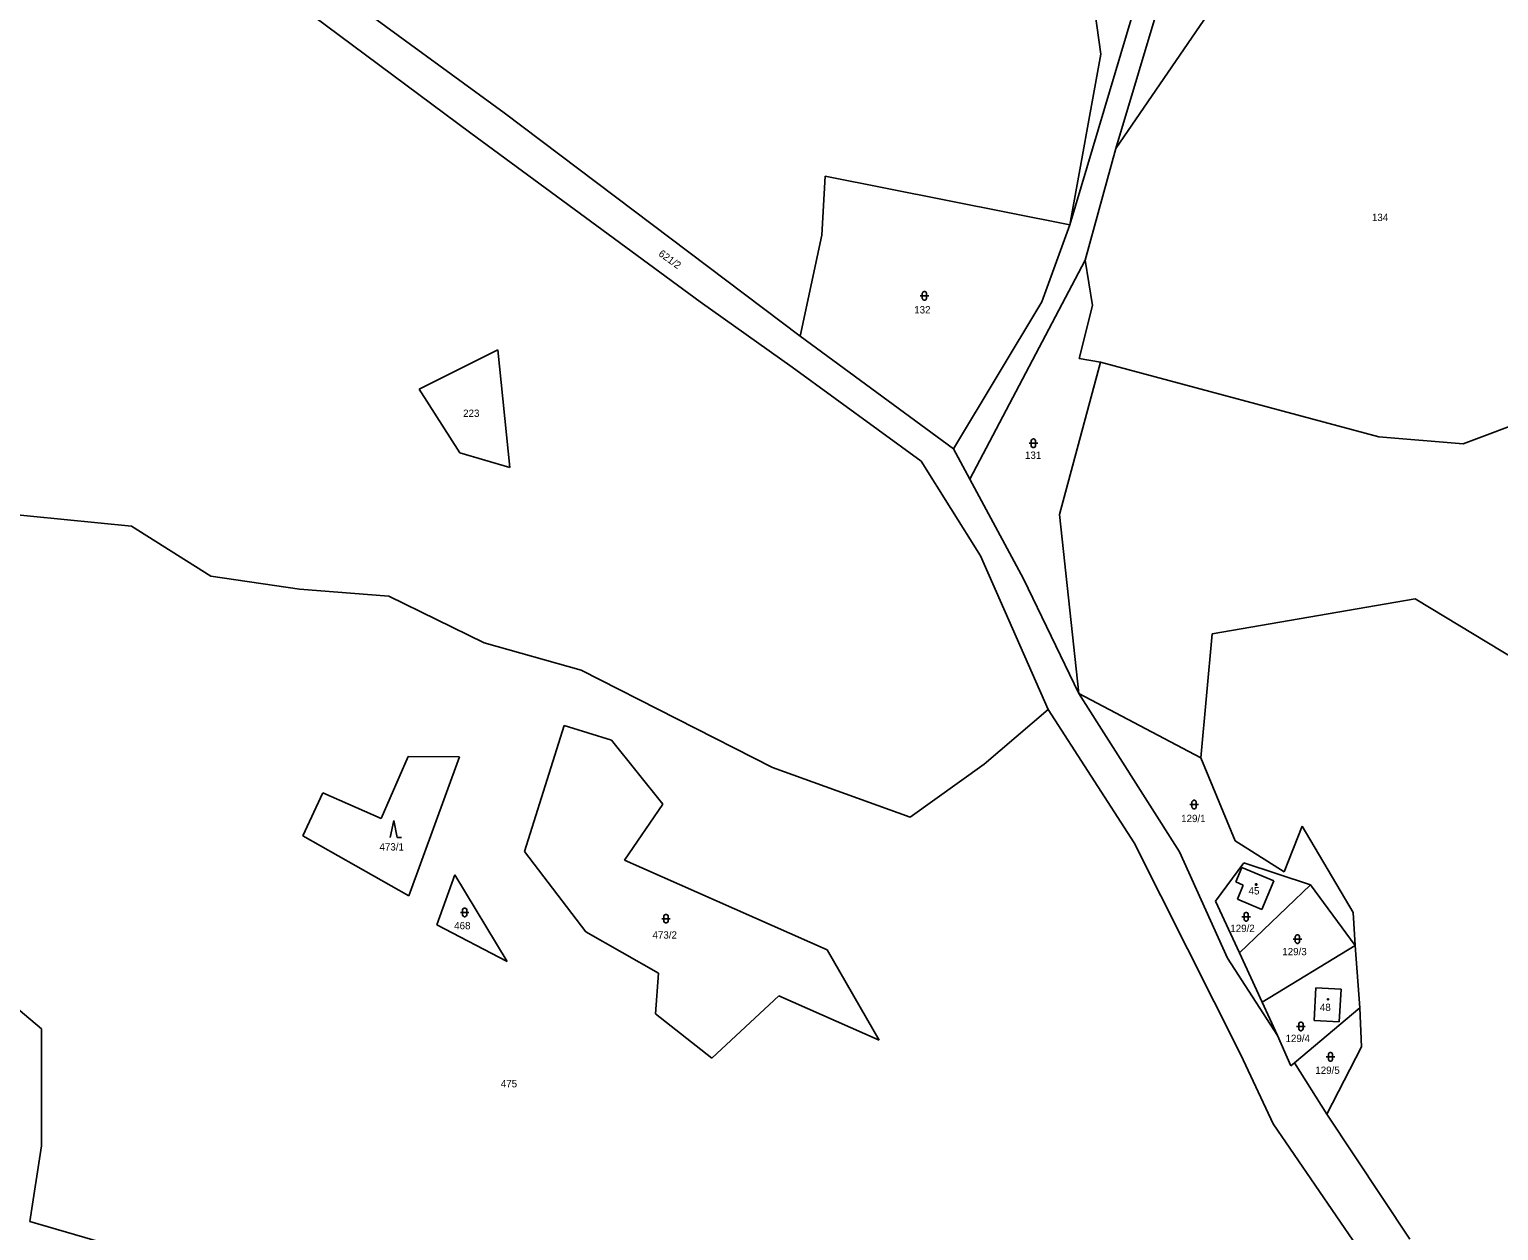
# Model space of a CAD drawing. Extents: x -794421 to -792735, y -1117671 to -1115559.
# Drawn here: x -793818.1 to -793476.5, y -1116696.2 to -1116417 of the extents above; entities that cross this region are included whole.
import ezdxf

# ---------------------------------------------------------------- set-up
doc = ezdxf.new("R2010")
doc.units = 0
for name, color, linetype in [('Vrstva 1', 7, 'Continuous'), ('Vrstva 14', 7, 'Continuous'), ('Vrstva 15', 7, 'Continuous'), ('Vrstva 23', 7, 'Continuous'), ('Vrstva 25', 7, 'Continuous')]:
    doc.layers.add(name, color=color, linetype=linetype)

msp = doc.modelspace()

# ---------------------------------------------------------------- linework, layer by layer
at = {"layer": 'Vrstva 1'}
for p, q in [((-793565.49, -1116444.67), (-793533.59, -1116338.16)), ((-793817.71, -1116356.03), (-793707.67, -1116436.43)), ((-793820.52, -1116362.92), (-793715.41, -1116441.11)), ((-793573.29, -1116390.8), (-793568.98, -1116422.79)), ((-793556.19, -1116395.36), (-793576.18, -1116462.41)), ((-793565.49, -1116444.67), (-793539.73, -1116407.1)), ((-793568.98, -1116422.79), (-793576.18, -1116462.41)), ((-793707.67, -1116436.43), (-793638.86, -1116488.32)), ((-793715.41, -1116441.11), (-793662.08, -1116480.35)), ((-793572.59, -1116470.68), (-793565.49, -1116444.67)), ((-793633.79, -1116464.83), (-793633.04, -1116451.11)), ((-793633.04, -1116451.11), (-793576.18, -1116462.41)), ((-793576.18, -1116462.41), (-793582.65, -1116480.35)), ((-793638.86, -1116488.32), (-793633.79, -1116464.83)), ((-793599.39, -1116521.55), (-793572.59, -1116470.68)), ((-793572.59, -1116470.68), (-793570.88, -1116481.22)), ((-793662.08, -1116480.35), (-793640.75, -1116495.51)), ((-793582.65, -1116480.35), (-793603.22, -1116514.51)), ((-793570.88, -1116481.22), (-793573.97, -1116493.48)), ((-793727.46, -1116500.6), (-793709.18, -1116491.49)), ((-793709.18, -1116491.49), (-793706.36, -1116518.83)), ((-793603.22, -1116514.51), (-793638.86, -1116488.32)), ((-793569.05, -1116494.39), (-793578.55, -1116529.8)), ((-793573.97, -1116493.48), (-793569.05, -1116494.39)), ((-793504.33, -1116511.72), (-793569.05, -1116494.39)), ((-793640.75, -1116495.51), (-793610.73, -1116517.36)), ((-793717.98, -1116515.4), (-793727.46, -1116500.6)), ((-793468.63, -1116507.3), (-793484.73, -1116513.33)), ((-793484.73, -1116513.33), (-793504.33, -1116511.72)), ((-793706.36, -1116518.83), (-793717.98, -1116515.4)), ((-793603.22, -1116514.51), (-793599.39, -1116521.55)), ((-793610.73, -1116517.36), (-793596.97, -1116539.36)), ((-793586.9, -1116544.73), (-793599.39, -1116521.55)), ((-793839.41, -1116527.98), (-793794.32, -1116532.47)), ((-793794.32, -1116532.47), (-793775.91, -1116544.13)), ((-793578.55, -1116529.8), (-793574.06, -1116571.38)), ((-793596.97, -1116539.36), (-793581.18, -1116575.07)), ((-793775.91, -1116544.13), (-793755.23, -1116547.16)), ((-793574.06, -1116571.38), (-793586.9, -1116544.73)), ((-793755.23, -1116547.16), (-793734.46, -1116548.75)), ((-793734.46, -1116548.75), (-793712.33, -1116559.56)), ((-793543.04, -1116557.47), (-793495.85, -1116549.36)), ((-793495.85, -1116549.36), (-793420.04, -1116595.36)), ((-793712.33, -1116559.56), (-793689.8, -1116565.98)), ((-793545.72, -1116586.36), (-793543.04, -1116557.47)), ((-793689.8, -1116565.98), (-793645.3, -1116588.59)), ((-793574.06, -1116571.38), (-793545.72, -1116586.36)), ((-793574.06, -1116571.38), (-793550.69, -1116608.2)), ((-793596.12, -1116587.78), (-793581.18, -1116575.07)), ((-793581.18, -1116575.07), (-793561.2, -1116606.1)), ((-793702.95, -1116608.11), (-793693.75, -1116578.84)), ((-793693.75, -1116578.84), (-793682.71, -1116582.26)), ((-793682.71, -1116582.26), (-793670.77, -1116597.08)), ((-793736.31, -1116600.42), (-793729.99, -1116586.05)), ((-793729.99, -1116586.05), (-793718.09, -1116586.11)), ((-793718.09, -1116586.11), (-793729.87, -1116618.38)), ((-793545.72, -1116586.36), (-793537.76, -1116605.64)), ((-793645.3, -1116588.59), (-793613.3, -1116600.12)), ((-793613.3, -1116600.12), (-793596.12, -1116587.78)), ((-793754.46, -1116604.44), (-793749.83, -1116594.43)), ((-793749.83, -1116594.43), (-793736.31, -1116600.42)), ((-793670.77, -1116597.08), (-793679.71, -1116610.15)), ((-793526.36, -1116612.82), (-793522.13, -1116602.23)), ((-793522.13, -1116602.23), (-793510.33, -1116622.28)), ((-793729.87, -1116618.38), (-793754.46, -1116604.44)), ((-793561.2, -1116606.1), (-793536.44, -1116655.39)), ((-793537.76, -1116605.64), (-793526.36, -1116612.82)), ((-793688.69, -1116626.8), (-793702.95, -1116608.11)), ((-793679.71, -1116610.15), (-793632.55, -1116630.98)), ((-793550.69, -1116608.2), (-793539.5, -1116632.92)), ((-793542.31, -1116619.66), (-793535.68, -1116610.77)), ((-793535.68, -1116610.77), (-793520.23, -1116615.82)), ((-793723.31, -1116625.18), (-793719.14, -1116613.55)), ((-793719.14, -1116613.55), (-793706.96, -1116633.65)), ((-793537.55, -1116615.19), (-793536.18, -1116611.85)), ((-793536.18, -1116611.85), (-793528.75, -1116614.91)), ((-793535.84, -1116615.95), (-793537.55, -1116615.19)), ((-793537.19, -1116619.18), (-793535.84, -1116615.95)), ((-793520.23, -1116615.82), (-793536.73, -1116631.68)), ((-793528.75, -1116614.91), (-793531.53, -1116621.55)), ((-793520.23, -1116615.82), (-793509.84, -1116629.98)), ((-793536.73, -1116631.68), (-793542.31, -1116619.66)), ((-793531.53, -1116621.55), (-793537.19, -1116619.18)), ((-793510.33, -1116622.28), (-793509.84, -1116629.98)), ((-793706.96, -1116633.65), (-793723.31, -1116625.18)), ((-793671.82, -1116636.39), (-793688.69, -1116626.8)), ((-793632.55, -1116630.98), (-793620.47, -1116651.92)), ((-793509.84, -1116629.98), (-793531.46, -1116643.1)), ((-793509.84, -1116629.98), (-793508.72, -1116644.42)), ((-793539.5, -1116632.92), (-793527.92, -1116650.91)), ((-793531.46, -1116643.1), (-793536.73, -1116631.68)), ((-793672.52, -1116645.82), (-793671.82, -1116636.39)), ((-793826.93, -1116639.52), (-793815.21, -1116649.33)), ((-793643.81, -1116641.63), (-793659.41, -1116656.16)), ((-793620.47, -1116651.92), (-793643.81, -1116641.63)), ((-793519.35, -1116647.36), (-793518.94, -1116639.78)), ((-793518.94, -1116639.78), (-793513.12, -1116640.07)), ((-793513.12, -1116640.07), (-793513.51, -1116647.67)), ((-793531.46, -1116643.1), (-793527.92, -1116650.91)), ((-793508.72, -1116644.42), (-793523.95, -1116657.24)), ((-793508.72, -1116644.42), (-793508.34, -1116653.49)), ((-793659.41, -1116656.16), (-793672.52, -1116645.82)), ((-793513.51, -1116647.67), (-793519.35, -1116647.36)), ((-793815.21, -1116649.33), (-793815.21, -1116676.5)), ((-793527.92, -1116650.91), (-793524.75, -1116657.91)), ((-793536.44, -1116655.39), (-793528.9, -1116671.42)), ((-793508.34, -1116653.49), (-793516.41, -1116669.13)), ((-793523.95, -1116657.24), (-793524.75, -1116657.91)), ((-793516.41, -1116669.13), (-793523.95, -1116657.24)), ((-793516.41, -1116669.13), (-793497.1, -1116698.22)), ((-793528.9, -1116671.42), (-793509.4, -1116699.91)), ((-793815.21, -1116676.5), (-793817.93, -1116694.07)), ((-793817.93, -1116694.07), (-793767.94, -1116708.64))]:
    msp.add_line(p, q, dxfattribs=at)
at = {"layer": 'Vrstva 23'}
for p, q in [((-793610.26, -1116478.03), (-793610.06, -1116477.93)), ((-793610.06, -1116477.93), (-793609.86, -1116477.93)), ((-793609.86, -1116477.93), (-793609.66, -1116478.03)), ((-793610.96, -1116478.93), (-793608.96, -1116478.93)), ((-793610.46, -1116478.33), (-793610.36, -1116478.13)), ((-793610.46, -1116479.53), (-793610.46, -1116478.33)), ((-793610.36, -1116479.73), (-793610.46, -1116479.53)), ((-793610.36, -1116478.13), (-793610.26, -1116478.03)), ((-793610.26, -1116479.83), (-793610.36, -1116479.73)), ((-793610.06, -1116479.93), (-793610.26, -1116479.83)), ((-793609.86, -1116479.93), (-793610.06, -1116479.93)), ((-793609.66, -1116479.83), (-793609.86, -1116479.93)), ((-793609.66, -1116478.03), (-793609.56, -1116478.13)), ((-793609.56, -1116479.73), (-793609.66, -1116479.83)), ((-793609.56, -1116478.13), (-793609.46, -1116478.33)), ((-793609.46, -1116479.53), (-793609.56, -1116479.73)), ((-793609.46, -1116478.33), (-793609.46, -1116479.53)), ((-793585.64, -1116513.21), (-793583.64, -1116513.21)), ((-793585.14, -1116512.61), (-793585.04, -1116512.41)), ((-793585.14, -1116513.81), (-793585.14, -1116512.61)), ((-793585.04, -1116514.01), (-793585.14, -1116513.81)), ((-793585.04, -1116512.41), (-793584.94, -1116512.31)), ((-793584.94, -1116514.11), (-793585.04, -1116514.01)), ((-793584.94, -1116512.31), (-793584.74, -1116512.21)), ((-793584.74, -1116514.21), (-793584.94, -1116514.11)), ((-793584.74, -1116512.21), (-793584.54, -1116512.21)), ((-793584.54, -1116514.21), (-793584.74, -1116514.21)), ((-793584.54, -1116512.21), (-793584.34, -1116512.31)), ((-793584.34, -1116514.11), (-793584.54, -1116514.21)), ((-793584.34, -1116512.31), (-793584.24, -1116512.41)), ((-793584.24, -1116514.01), (-793584.34, -1116514.11)), ((-793584.24, -1116512.41), (-793584.14, -1116512.61)), ((-793584.14, -1116513.81), (-793584.24, -1116514.01)), ((-793584.14, -1116512.61), (-793584.14, -1116513.81)), ((-793548.27, -1116597.19), (-793546.27, -1116597.19)), ((-793547.77, -1116596.59), (-793547.67, -1116596.39)), ((-793547.77, -1116597.79), (-793547.77, -1116596.59)), ((-793547.67, -1116596.39), (-793547.57, -1116596.29)), ((-793547.57, -1116596.29), (-793547.37, -1116596.19)), ((-793547.37, -1116596.19), (-793547.17, -1116596.19)), ((-793547.17, -1116596.19), (-793546.97, -1116596.29)), ((-793546.97, -1116596.29), (-793546.87, -1116596.39)), ((-793546.87, -1116596.39), (-793546.77, -1116596.59)), ((-793546.77, -1116596.59), (-793546.77, -1116597.79)), ((-793734.17, -1116604.88), (-793733.37, -1116600.88)), ((-793733.37, -1116600.88), (-793732.57, -1116604.88)), ((-793547.67, -1116597.99), (-793547.77, -1116597.79)), ((-793547.57, -1116598.09), (-793547.67, -1116597.99)), ((-793547.37, -1116598.19), (-793547.57, -1116598.09)), ((-793547.17, -1116598.19), (-793547.37, -1116598.19)), ((-793546.97, -1116598.09), (-793547.17, -1116598.19)), ((-793546.87, -1116597.99), (-793546.97, -1116598.09)), ((-793546.77, -1116597.79), (-793546.87, -1116597.99)), ((-793732.57, -1116604.88), (-793731.57, -1116604.88)), ((-793717.26, -1116621.45), (-793717.16, -1116621.35)), ((-793717.16, -1116621.35), (-793716.96, -1116621.25)), ((-793716.96, -1116621.25), (-793716.76, -1116621.25)), ((-793716.76, -1116621.25), (-793716.56, -1116621.35)), ((-793716.56, -1116621.35), (-793716.46, -1116621.45)), ((-793717.86, -1116622.25), (-793715.86, -1116622.25)), ((-793717.36, -1116621.65), (-793717.26, -1116621.45)), ((-793717.36, -1116622.85), (-793717.36, -1116621.65)), ((-793717.26, -1116623.05), (-793717.36, -1116622.85)), ((-793717.16, -1116623.15), (-793717.26, -1116623.05)), ((-793716.96, -1116623.25), (-793717.16, -1116623.15)), ((-793716.76, -1116623.25), (-793716.96, -1116623.25)), ((-793716.56, -1116623.15), (-793716.76, -1116623.25)), ((-793716.46, -1116623.05), (-793716.56, -1116623.15)), ((-793716.46, -1116621.45), (-793716.36, -1116621.65)), ((-793716.36, -1116622.85), (-793716.46, -1116623.05)), ((-793716.36, -1116621.65), (-793716.36, -1116622.85)), ((-793671.05, -1116623.72), (-793669.05, -1116623.72)), ((-793670.55, -1116623.12), (-793670.45, -1116622.92)), ((-793670.55, -1116624.32), (-793670.55, -1116623.12)), ((-793670.45, -1116624.52), (-793670.55, -1116624.32)), ((-793670.45, -1116622.92), (-793670.35, -1116622.82)), ((-793670.35, -1116624.62), (-793670.45, -1116624.52)), ((-793670.35, -1116622.82), (-793670.15, -1116622.72)), ((-793670.15, -1116624.72), (-793670.35, -1116624.62)), ((-793670.15, -1116622.72), (-793669.95, -1116622.72)), ((-793669.95, -1116624.72), (-793670.15, -1116624.72)), ((-793669.95, -1116622.72), (-793669.75, -1116622.82)), ((-793669.75, -1116624.62), (-793669.95, -1116624.72)), ((-793669.75, -1116622.82), (-793669.65, -1116622.92)), ((-793669.65, -1116624.52), (-793669.75, -1116624.62)), ((-793669.65, -1116622.92), (-793669.55, -1116623.12)), ((-793669.55, -1116624.32), (-793669.65, -1116624.52)), ((-793669.55, -1116623.12), (-793669.55, -1116624.32)), ((-793536.17, -1116623.27), (-793534.17, -1116623.27)), ((-793535.67, -1116622.67), (-793535.57, -1116622.47)), ((-793535.67, -1116623.87), (-793535.67, -1116622.67)), ((-793535.57, -1116624.07), (-793535.67, -1116623.87)), ((-793535.57, -1116622.47), (-793535.47, -1116622.37)), ((-793535.47, -1116624.17), (-793535.57, -1116624.07)), ((-793535.47, -1116622.37), (-793535.27, -1116622.27)), ((-793535.27, -1116624.27), (-793535.47, -1116624.17)), ((-793535.27, -1116622.27), (-793535.07, -1116622.27)), ((-793535.07, -1116624.27), (-793535.27, -1116624.27)), ((-793535.07, -1116622.27), (-793534.87, -1116622.37)), ((-793534.87, -1116624.17), (-793535.07, -1116624.27)), ((-793534.87, -1116622.37), (-793534.77, -1116622.47)), ((-793534.77, -1116624.07), (-793534.87, -1116624.17)), ((-793534.77, -1116622.47), (-793534.67, -1116622.67)), ((-793534.67, -1116623.87), (-793534.77, -1116624.07)), ((-793534.67, -1116622.67), (-793534.67, -1116623.87)), ((-793523.75, -1116627.87), (-793523.65, -1116627.67)), ((-793523.75, -1116629.07), (-793523.75, -1116627.87)), ((-793523.65, -1116627.67), (-793523.55, -1116627.57)), ((-793523.55, -1116627.57), (-793523.35, -1116627.47)), ((-793523.35, -1116627.47), (-793523.15, -1116627.47)), ((-793523.15, -1116627.47), (-793522.95, -1116627.57)), ((-793522.95, -1116627.57), (-793522.85, -1116627.67)), ((-793522.85, -1116627.67), (-793522.75, -1116627.87)), ((-793522.75, -1116627.87), (-793522.75, -1116629.07)), ((-793524.25, -1116628.47), (-793522.25, -1116628.47)), ((-793523.65, -1116629.27), (-793523.75, -1116629.07)), ((-793523.55, -1116629.37), (-793523.65, -1116629.27)), ((-793523.35, -1116629.47), (-793523.55, -1116629.37)), ((-793523.15, -1116629.47), (-793523.35, -1116629.47)), ((-793522.95, -1116629.37), (-793523.15, -1116629.47)), ((-793522.85, -1116629.27), (-793522.95, -1116629.37)), ((-793522.75, -1116629.07), (-793522.85, -1116629.27)), ((-793522.95, -1116648.16), (-793522.85, -1116647.96)), ((-793522.95, -1116649.36), (-793522.95, -1116648.16)), ((-793522.85, -1116647.96), (-793522.75, -1116647.86)), ((-793522.75, -1116647.86), (-793522.55, -1116647.76)), ((-793522.55, -1116647.76), (-793522.35, -1116647.76)), ((-793522.35, -1116647.76), (-793522.15, -1116647.86)), ((-793522.15, -1116647.86), (-793522.05, -1116647.96)), ((-793522.05, -1116647.96), (-793521.95, -1116648.16)), ((-793521.95, -1116648.16), (-793521.95, -1116649.36)), ((-793523.45, -1116648.76), (-793521.45, -1116648.76)), ((-793522.85, -1116649.56), (-793522.95, -1116649.36)), ((-793522.75, -1116649.66), (-793522.85, -1116649.56)), ((-793522.55, -1116649.76), (-793522.75, -1116649.66)), ((-793522.35, -1116649.76), (-793522.55, -1116649.76)), ((-793522.15, -1116649.66), (-793522.35, -1116649.76)), ((-793522.05, -1116649.56), (-793522.15, -1116649.66)), ((-793521.95, -1116649.36), (-793522.05, -1116649.56)), ((-793516.06, -1116655.24), (-793515.96, -1116655.04)), ((-793516.06, -1116656.44), (-793516.06, -1116655.24)), ((-793515.96, -1116655.04), (-793515.86, -1116654.94)), ((-793515.86, -1116654.94), (-793515.66, -1116654.84)), ((-793515.66, -1116654.84), (-793515.46, -1116654.84)), ((-793515.46, -1116654.84), (-793515.26, -1116654.94)), ((-793515.26, -1116654.94), (-793515.16, -1116655.04)), ((-793515.16, -1116655.04), (-793515.06, -1116655.24)), ((-793515.06, -1116655.24), (-793515.06, -1116656.44)), ((-793516.56, -1116655.84), (-793514.56, -1116655.84)), ((-793515.96, -1116656.64), (-793516.06, -1116656.44)), ((-793515.86, -1116656.74), (-793515.96, -1116656.64)), ((-793515.66, -1116656.84), (-793515.86, -1116656.74)), ((-793515.46, -1116656.84), (-793515.66, -1116656.84)), ((-793515.26, -1116656.74), (-793515.46, -1116656.84)), ((-793515.16, -1116656.64), (-793515.26, -1116656.74)), ((-793515.06, -1116656.44), (-793515.16, -1116656.64))]:
    msp.add_line(p, q, dxfattribs=at)
at = {"layer": 'Vrstva 25'}
for p, q in [((-793532.99, -1116615.65), (-793532.69, -1116615.65)), ((-793532.99, -1116615.95), (-793532.99, -1116615.65)), ((-793532.69, -1116615.95), (-793532.99, -1116615.95)), ((-793532.69, -1116615.65), (-793532.69, -1116615.95)), ((-793516.29, -1116642.32), (-793515.99, -1116642.32)), ((-793516.29, -1116642.62), (-793516.29, -1116642.32)), ((-793515.99, -1116642.62), (-793516.29, -1116642.62)), ((-793515.99, -1116642.32), (-793515.99, -1116642.62))]:
    msp.add_line(p, q, dxfattribs=at)

# ---------------------------------------------------------------- texts
at = {"layer": 'Vrstva 14'}
for s, p in [('134', (-793505.936, -1116461.56)), ('132', (-793612.35, -1116483.03)), ('223', (-793717.226, -1116507.08)), ('131', (-793586.593, -1116516.83)), ('129/1', (-793550.286, -1116601.27)), ('473/1', (-793736.666, -1116607.87)), ('468', (-793719.302, -1116626.18)), ('473/2', (-793673.192, -1116628.35)), ('129/2', (-793538.863, -1116626.82)), ('129/3', (-793526.773, -1116632.22)), ('129/4', (-793526.019, -1116652.39)), ('129/5', (-793519.099, -1116659.8)), ('475', (-793708.465, -1116662.92))]:
    msp.add_text(s, height=1.7, dxfattribs=at).set_placement(p)
msp.add_text('621/2', height=1.7, rotation=324.20187, dxfattribs=at).set_placement((-793671.95, -1116469.472))
at = {"layer": 'Vrstva 15'}
for s, p in [('45', (-793534.609, -1116618.09)), ('48', (-793518.032, -1116645.17))]:
    msp.add_text(s, height=1.7, dxfattribs=at).set_placement(p)

doc.saveas('drawing.dxf')
